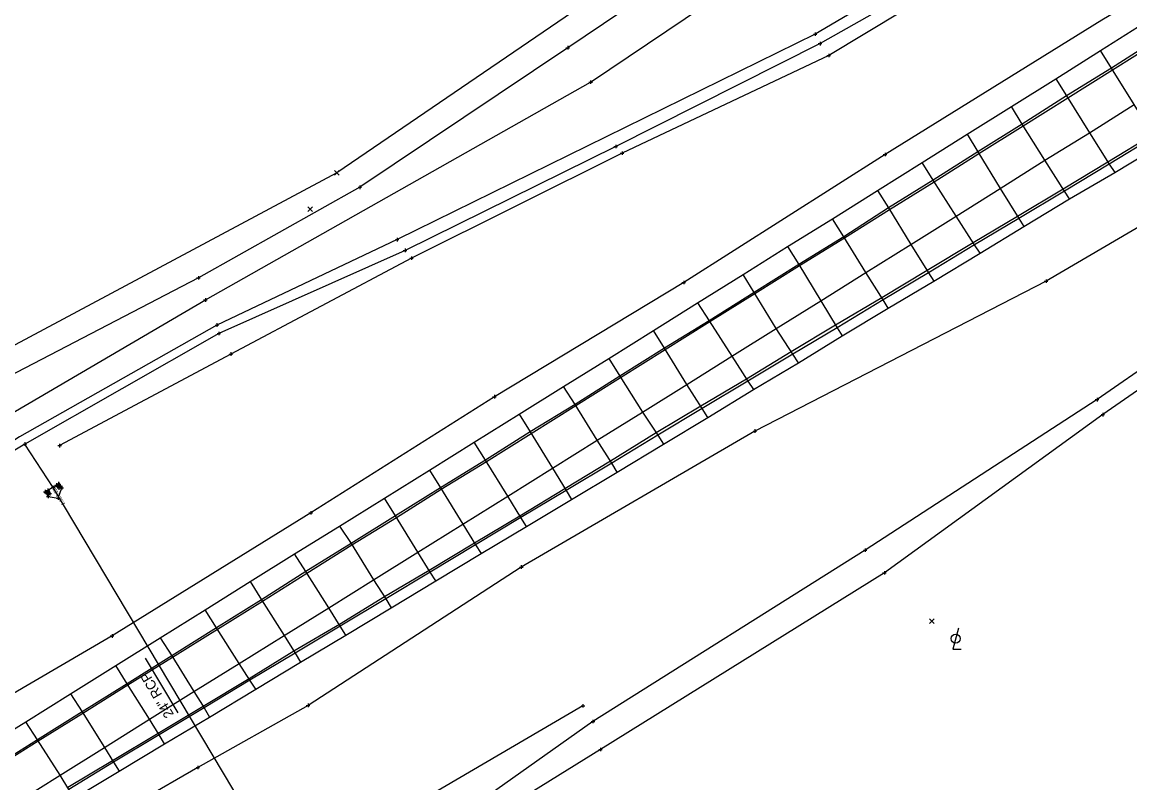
# Model space of a CAD drawing. Extents: x 207090 to 277928, y 600777 to 621109.
# Drawn here: x 260128.7 to 260443.9, y 612310 to 612526.4 of the extents above; entities that cross this region are included whole.
import ezdxf

# ---------------------------------------------------------------- set-up
doc = ezdxf.new("R2010")
doc.units = 0
for name, color, linetype in [('ATDIMS', 7, 'Continuous'), ('BR_X_SV_Abut', 7, 'Continuous'), ('DR_X_Ditch', 7, 'Continuous'), ('DR_X_Headwall', 7, 'Continuous'), ('DR_X_Storm_Sewer', 7, 'Continuous'), ('DR_X_Text', 7, 'Continuous'), ('PM_P_Edge_Line', 7, 'Continuous'), ('PM_P_Lane_Line', 7, 'Continuous'), ('PM_P_Stop_Line', 7, 'Continuous'), ('PM_X_Edge_Line', 7, 'Continuous'), ('PV_X_EOP', 7, 'Continuous'), ('PV_X_Joint', 7, 'Continuous'), ('SC_ProfileRun2', 7, 'Continuous'), ('SV_X_Break_Lines', 7, 'Continuous'), ('SV_X_Terrain_Boundary', 7, 'Continuous'), ('SV_X_Toe_of_Slope', 7, 'Continuous')]:
    doc.layers.add(name, color=color, linetype=linetype)

msp = doc.modelspace()

# ---------------------------------------------------------------- linework, layer by layer
at = {"layer": 'BR_X_SV_Abut'}
msp.add_lwpolyline([(260395.11, 612354.01), (260393.53, 612348.02), (260395.9, 612348.02)], dxfattribs=at)
msp.add_circle((260394.32, 612351.05), 1.3, dxfattribs=at)
at = {"layer": 'DR_X_Ditch'}
for points in [[(260965.76, 612646.3), (260903.89, 612637.59), (260846.21, 612640.66), (260788.21, 612648.32), (260712.08, 612649.13), (260650.53, 612639.93), (260587.71, 612626.03), (260540.4, 612612.72), (260479.82, 612585.9), (260420.03, 612556.72), (260355.72, 612520.34), (260297.57, 612491.05), (260237.63, 612461.5), (260184.65, 612437.88), (260129.42, 612406.42), (260102.9, 612390.57), (260048.34, 612353.6), (259987.69, 612317.19), (259901.67, 612280.03), (259846.55, 612257.32), (259766.99, 612243.21), (259700.14, 612233.86)], [(260980.17, 612470.92), (260981.01, 612514.45), (260979.66, 612549.25), (260978.64, 612555.37), (260908.69, 612562.28), (260843.91, 612565.34), (260762.22, 612565.34), (260693.51, 612556.33), (260617.41, 612526.56), (260561.75, 612499.61), (260504.79, 612467.62), (260434.56, 612419.04), (260368.56, 612376.23), (260291.11, 612327.46), (260243.23, 612293.63), (260221.27, 612279.24), (260214.19, 612277.7), (260205.93, 612279.66)], [(260137.52, 612394.05), (260129.42, 612406.42)]]:
    msp.add_lwpolyline(points, dxfattribs=at)
at = {"layer": 'DR_X_Headwall'}
for p, q in [((260139.64, 612394.15), (260139.21, 612394.9)), ((260136.04, 612392.11), (260135.41, 612392.64))]:
    msp.add_line(p, q, dxfattribs=at)
for points in [[(260139.21, 612394.9), (260138.64, 612394.46), (260139.1, 612393.91), (260139.64, 612394.15)], [(260135.41, 612392.64), (260136, 612393.06), (260136.53, 612392.32), (260136.04, 612392.11)]]:
    msp.add_lwpolyline(points, dxfattribs=at)
at = {"layer": 'DR_X_Storm_Sewer'}
msp.add_line((260205.25, 612280.38), (260137.52, 612394.05), dxfattribs=at)
at = {"layer": 'DR_X_Text'}
msp.add_line((260163.68, 612345.46), (260172.92, 612329.95), dxfattribs=at)
at = {"layer": 'PM_P_Edge_Line'}
for points in [[(259696.19, 612249.37), (259765.47, 612259.57), (259838.8, 612280.72), (259895.42, 612296.27), (259981.86, 612326.52), (260044.12, 612359.9), (260097.15, 612394.53), (260124, 612414.15), (260180.79, 612447.41), (260290.45, 612509.39), (260339.08, 612542.14), (260411.33, 612573.42), (260464.85, 612610.64), (260533.51, 612630.82), (260578.81, 612648.35), (260650.05, 612658.82), (260707.7, 612667.46), (260792.67, 612670.85), (260847.64, 612666.05), (260906.75, 612659.27), (260964.74, 612649.27), (260965.76, 612646.3), (260968.73, 612643.36)], [(260968.73, 612643.36), (260902.74, 612623.34), (260846.31, 612624.57), (260788.34, 612627.98), (260717.27, 612628.63), (260652.8, 612617.17), (260594.62, 612604.25), (260547.65, 612587.51), (260494.06, 612561.48), (260435.88, 612526.99), (260374.24, 612488.77), (260316.93, 612452.38), (260263.05, 612419.87), (260210.79, 612386.85), (260154.25, 612351.81), (260072.66, 612304.2), (260017.02, 612269.09), (259922.67, 612223.96), (259862.48, 612201.08), (259773.94, 612184.08), (259709.47, 612174.19)], [(260996.77, 612473.28), (260998.48, 612548.29), (260988.85, 612564.56), (260906.86, 612575.54), (260845.98, 612579.97), (260758.62, 612581.58), (260693.48, 612576.37), (260609.06, 612545.38), (260552.2, 612527.51), (260484.57, 612490.49), (260420.05, 612452.77), (260337.19, 612410.11), (260270.71, 612371.43), (260210.01, 612332.07), (260178.64, 612314.39), (260129.43, 612285.91), (260084.69, 612259.04), (260045.01, 612227.43), (260009.91, 612199.93)], [(260976.29, 612470.03), (260970.41, 612512.82), (260969.69, 612547.81), (260964.96, 612546.01), (260907.75, 612553.29), (260842.6, 612550.07), (260764.48, 612554.75), (260693.91, 612550.19), (260623.11, 612514), (260563.35, 612494.47), (260507.46, 612464.18), (260436.22, 612414.79), (260374.03, 612369.76), (260293.26, 612319.49), (260245.08, 612289.62), (260217.93, 612273.45)]]:
    msp.add_lwpolyline(points, dxfattribs=at)
at = {"layer": 'PM_P_Lane_Line'}
msp.add_lwpolyline([(260938.98, 612687.53), (260905.67, 612669.26), (260848.25, 612675.38), (260795.41, 612680.92), (260704.93, 612686.62), (260648.32, 612680.48), (260579.89, 612672.71), (260529.06, 612649.65), (260401.46, 612592.11), (260375.93, 612580.54), (260334.15, 612552.98), (260283.92, 612519.17), (260224.77, 612479.46), (260178.82, 612453.71), (260087.02, 612406.01), (260035.98, 612379.41), (259972.28, 612348.23), (259887.97, 612316.7), (259832.19, 612304.21), (259761.95, 612288.66), (259689.59, 612272.72)], dxfattribs=at)
at = {"layer": 'PM_P_Stop_Line'}
for p, q in [((260354.36, 612523.53), (260354.36, 612522.53)), ((260353.86, 612523.03), (260354.86, 612523.03)), ((260354.36, 612523.03), (260354.36, 612523.03)), ((260355.22, 612520.34), (260356.22, 612520.34)), ((260355.72, 612520.84), (260355.72, 612519.84)), ((260355.72, 612520.34), (260355.72, 612520.34)), ((260283.42, 612519.17), (260284.42, 612519.17)), ((260283.92, 612519.67), (260283.92, 612518.67)), ((260283.92, 612519.17), (260283.92, 612519.17)), ((260358.19, 612517.47), (260358.19, 612516.47)), ((260357.69, 612516.97), (260358.69, 612516.97)), ((260358.19, 612516.97), (260358.19, 612516.97)), ((260289.95, 612509.39), (260290.95, 612509.39)), ((260290.45, 612509.89), (260290.45, 612508.89)), ((260290.45, 612509.39), (260290.45, 612509.39)), ((260297.07, 612491.05), (260298.07, 612491.05)), ((260297.57, 612491.55), (260297.57, 612490.55)), ((260297.57, 612491.05), (260297.57, 612491.05)), ((260298.89, 612489.18), (260299.89, 612489.18)), ((260299.39, 612489.68), (260299.39, 612488.68)), ((260299.39, 612489.18), (260299.39, 612489.18)), ((260373.74, 612488.77), (260374.74, 612488.77)), ((260374.24, 612489.27), (260374.24, 612488.27)), ((260374.24, 612488.77), (260374.24, 612488.77)), ((260224.27, 612479.46), (260225.27, 612479.46)), ((260224.77, 612479.96), (260224.77, 612478.96)), ((260224.77, 612479.46), (260224.77, 612479.46)), ((260234.88, 612464.57), (260235.88, 612464.57)), ((260235.38, 612465.07), (260235.38, 612464.07)), ((260235.38, 612464.57), (260235.38, 612464.57)), ((260237.13, 612461.5), (260238.13, 612461.5)), ((260237.63, 612462), (260237.63, 612461)), ((260237.63, 612461.5), (260237.63, 612461.5)), ((260238.97, 612459.31), (260239.97, 612459.31)), ((260239.47, 612459.81), (260239.47, 612458.81)), ((260239.47, 612459.31), (260239.47, 612459.31)), ((260178.82, 612454.21), (260178.82, 612453.21)), ((260178.32, 612453.71), (260179.32, 612453.71)), ((260178.82, 612453.71), (260178.82, 612453.71)), ((260316.43, 612452.38), (260317.43, 612452.38)), ((260316.93, 612452.88), (260316.93, 612451.88)), ((260316.93, 612452.38), (260316.93, 612452.38)), ((260419.55, 612452.77), (260420.55, 612452.77)), ((260420.05, 612453.27), (260420.05, 612452.27)), ((260420.05, 612452.77), (260420.05, 612452.77)), ((260180.79, 612447.91), (260180.79, 612446.91)), ((260180.29, 612447.41), (260181.29, 612447.41)), ((260180.79, 612447.41), (260180.79, 612447.41)), ((260183.57, 612440.26), (260184.57, 612440.26)), ((260184.07, 612440.76), (260184.07, 612439.76)), ((260184.07, 612440.26), (260184.07, 612440.26)), ((260184.65, 612438.38), (260184.65, 612437.38)), ((260184.15, 612437.88), (260185.15, 612437.88)), ((260184.65, 612437.88), (260184.65, 612437.88)), ((260187.54, 612432.01), (260188.54, 612432.01)), ((260188.04, 612432.51), (260188.04, 612431.51)), ((260188.04, 612432.01), (260188.04, 612432.01)), ((260262.55, 612419.87), (260263.55, 612419.87)), ((260263.05, 612420.37), (260263.05, 612419.37)), ((260263.05, 612419.87), (260263.05, 612419.87)), ((260434.56, 612419.54), (260434.56, 612418.54)), ((260434.06, 612419.04), (260435.06, 612419.04)), ((260434.56, 612419.04), (260434.56, 612419.04)), ((260435.72, 612414.79), (260436.72, 612414.79)), ((260436.22, 612415.29), (260436.22, 612414.29)), ((260436.22, 612414.79), (260436.22, 612414.79)), ((260336.69, 612410.11), (260337.69, 612410.11)), ((260337.19, 612410.61), (260337.19, 612409.61)), ((260337.19, 612410.11), (260337.19, 612410.11)), ((260129.42, 612406.92), (260129.42, 612405.92)), ((260128.92, 612406.42), (260129.92, 612406.42)), ((260129.42, 612406.42), (260129.42, 612406.42)), ((260138.81, 612405.97), (260139.81, 612405.97)), ((260139.31, 612406.47), (260139.31, 612405.47)), ((260139.31, 612405.97), (260139.31, 612405.97)), ((260137.92, 612394.74), (260138.92, 612394.74)), ((260138.14, 612394.46), (260139.14, 612394.46)), ((260138.42, 612395.24), (260138.42, 612394.24)), ((260138.42, 612394.74), (260138.42, 612394.74)), ((260138.5, 612395.13), (260139.5, 612395.13)), ((260138.64, 612394.96), (260138.64, 612393.96)), ((260138.64, 612394.46), (260138.64, 612394.46)), ((260138.71, 612394.9), (260139.71, 612394.9)), ((260139, 612395.63), (260139, 612394.63)), ((260139, 612395.13), (260139, 612395.13)), ((260139.1, 612394.41), (260139.1, 612393.41)), ((260139.14, 612394.15), (260140.14, 612394.15)), ((260139.21, 612395.4), (260139.21, 612394.4)), ((260139.21, 612394.9), (260139.21, 612394.9)), ((260139.64, 612394.65), (260139.64, 612393.65)), ((260139.64, 612394.15), (260139.64, 612394.15)), ((260139.91, 612394.49), (260139.91, 612393.49)), ((260134.74, 612392.86), (260135.74, 612392.86)), ((260134.91, 612392.64), (260135.91, 612392.64)), ((260135.24, 612393.36), (260135.24, 612392.36)), ((260135.24, 612392.86), (260135.24, 612392.86)), ((260135.41, 612393.14), (260135.41, 612392.14)), ((260135.41, 612392.64), (260135.41, 612392.64)), ((260135.43, 612393.22), (260136.43, 612393.22)), ((260135.5, 612393.06), (260136.5, 612393.06)), ((260135.54, 612392.11), (260136.54, 612392.11)), ((260135.55, 612391.48), (260136.55, 612391.48)), ((260135.93, 612393.72), (260135.93, 612392.72)), ((260135.93, 612393.22), (260135.93, 612393.22)), ((260136, 612393.56), (260136, 612392.56)), ((260136, 612393.06), (260136, 612393.06)), ((260136.03, 612392.32), (260137.03, 612392.32)), ((260136.04, 612392.61), (260136.04, 612391.61)), ((260136.04, 612392.11), (260136.04, 612392.11)), ((260136.05, 612391.98), (260136.05, 612390.98)), ((260136.05, 612391.48), (260136.05, 612391.48)), ((260136.53, 612392.82), (260136.53, 612391.82)), ((260136.53, 612392.32), (260136.53, 612392.32)), ((260138.43, 612391.05), (260139.43, 612391.05)), ((260138.6, 612393.91), (260139.6, 612393.91)), ((260138.93, 612391.55), (260138.93, 612390.55)), ((260138.93, 612391.05), (260138.93, 612391.05)), ((260139.1, 612393.91), (260139.1, 612393.91)), ((260139.41, 612393.99), (260140.41, 612393.99)), ((260139.91, 612393.99), (260139.91, 612393.99)), ((260210.29, 612386.85), (260211.29, 612386.85)), ((260210.79, 612387.35), (260210.79, 612386.35)), ((260210.79, 612386.85), (260210.79, 612386.85)), ((260368.06, 612376.23), (260369.06, 612376.23)), ((260368.56, 612376.73), (260368.56, 612375.73)), ((260368.56, 612376.23), (260368.56, 612376.23)), ((260270.21, 612371.43), (260271.21, 612371.43)), ((260270.71, 612371.93), (260270.71, 612370.93)), ((260270.71, 612371.43), (260270.71, 612371.43)), ((260373.53, 612369.76), (260374.53, 612369.76)), ((260374.03, 612370.26), (260374.03, 612369.26)), ((260374.03, 612369.76), (260374.03, 612369.76)), ((260153.75, 612351.81), (260154.75, 612351.81)), ((260154.25, 612352.31), (260154.25, 612351.31)), ((260154.25, 612351.81), (260154.25, 612351.81)), ((260209.51, 612332.07), (260210.51, 612332.07)), ((260210.01, 612332.57), (260210.01, 612331.57)), ((260210.01, 612332.07), (260210.01, 612332.07)), ((260287.75, 612331.94), (260288.75, 612331.94)), ((260288.25, 612332.44), (260288.25, 612331.44)), ((260288.25, 612331.94), (260288.25, 612331.94)), ((260291.11, 612327.96), (260291.11, 612326.96)), ((260290.61, 612327.46), (260291.61, 612327.46)), ((260291.11, 612327.46), (260291.11, 612327.46)), ((260292.76, 612319.49), (260293.76, 612319.49)), ((260293.26, 612319.99), (260293.26, 612318.99)), ((260293.26, 612319.49), (260293.26, 612319.49)), ((260178.14, 612314.39), (260179.14, 612314.39)), ((260178.64, 612314.89), (260178.64, 612313.89)), ((260178.64, 612314.39), (260178.64, 612314.39))]:
    msp.add_line(p, q, dxfattribs=at)
at = {"layer": 'PM_X_Edge_Line'}
for p, q in [((260217.56, 612482.94), (260218.89, 612484.28)), ((260217.56, 612484.28), (260218.89, 612482.94)), ((260209.99, 612472.53), (260211.33, 612473.86)), ((260209.99, 612473.86), (260211.33, 612472.53)), ((260386.84, 612355.37), (260388.17, 612356.7)), ((260386.84, 612356.7), (260388.17, 612355.37))]:
    msp.add_line(p, q, dxfattribs=at)
for points in [[(260120.5, 612314.04), (260133.19, 612321.98), (260145.97, 612329.84), (260158.74, 612337.86), (260171.43, 612345.82), (260184.21, 612353.79), (260197.04, 612361.71), (260209.72, 612369.66), (260222.48, 612377.7), (260235.17, 612385.52), (260247.93, 612393.61), (260260.77, 612401.44), (260273.49, 612409.38), (260286.2, 612417.36), (260298.94, 612425.38), (260311.67, 612433.34), (260324.34, 612441.24), (260337.21, 612449.2), (260349.86, 612457.17), (260362.67, 612465.09), (260375.49, 612473.14), (260388.22, 612481.04), (260400.9, 612489.06), (260413.52, 612496.94), (260426.25, 612504.91), (260438.93, 612512.92), (260451.68, 612520.87)], [(260450.47, 612494.35), (260437.67, 612486.59), (260424.94, 612478.97), (260411.88, 612471.19), (260399.33, 612463.64), (260386.24, 612455.75), (260373.31, 612448.01), (260360.16, 612440.24), (260347.5, 612432.67), (260334.83, 612424.86), (260321.76, 612417.15), (260309.08, 612409.57), (260296.1, 612401.54), (260283.14, 612393.69), (260270.31, 612385.93), (260257.36, 612378.22), (260244.49, 612370.43), (260231.76, 612362.95), (260218.93, 612355.05), (260206.01, 612347.45), (260193.23, 612339.63), (260180.19, 612331.77), (260167.36, 612324.09), (260154.37, 612316.33), (260141.62, 612308.67)]]:
    msp.add_lwpolyline(points, dxfattribs=at)
at = {"layer": 'PV_X_EOP'}
for points in [[(260116.92, 612319.48), (260129.68, 612327.37), (260142.42, 612335.33), (260155.28, 612343.37), (260167.92, 612351.27), (260180.74, 612359.29), (260193.56, 612367.28), (260206.19, 612375.13), (260219.01, 612383.09), (260231.77, 612391.01), (260244.54, 612398.99), (260257.26, 612406.95), (260270.08, 612414.92), (260282.71, 612422.8), (260295.59, 612430.76), (260308.31, 612438.72), (260320.84, 612446.56), (260333.85, 612454.62), (260346.5, 612462.6), (260359.29, 612470.53), (260372.12, 612478.56), (260384.76, 612486.47), (260397.56, 612494.57), (260410.2, 612502.46), (260422.83, 612510.35), (260435.51, 612518.34), (260448.19, 612526.39)], [(260143.47, 612305.66), (260156.28, 612313.32), (260169.21, 612321.13), (260181.95, 612328.74), (260195.2, 612336.69), (260207.92, 612344.32), (260220.78, 612352.06), (260233.67, 612359.79), (260246.39, 612367.46), (260259.28, 612375.28), (260272.17, 612382.92), (260284.98, 612390.66), (260298, 612398.44), (260311.18, 612406.4), (260323.8, 612413.92), (260336.8, 612421.91), (260349.58, 612429.48), (260362.06, 612437.2), (260375.15, 612445.09), (260388.11, 612452.74), (260401.31, 612460.69), (260413.75, 612468.26), (260426.73, 612476.21), (260439.61, 612483.66), (260452.33, 612491.36)]]:
    msp.add_lwpolyline(points, dxfattribs=at)
at = {"layer": 'PV_X_Joint'}
for points in [[(260451.34, 612521.41), (260438.64, 612513.4), (260425.9, 612505.47), (260413.24, 612497.39), (260400.6, 612489.55), (260387.93, 612481.51), (260375.19, 612473.63)], [(260452.33, 612491.36), (260450.83, 612493.77), (260445.08, 612503), (260438.64, 612513.4), (260435.51, 612518.34)], [(260422.83, 612510.35), (260425.9, 612505.47), (260432.43, 612495), (260438, 612486.06), (260439.61, 612483.66)], [(260126.73, 612304.22), (260139.48, 612312.18), (260152.08, 612320.08), (260164.9, 612328.12), (260177.56, 612335.99), (260190.41, 612344), (260203.21, 612351.96), (260215.95, 612359.82), (260228.67, 612367.8), (260241.25, 612375.69), (260254.06, 612383.63), (260266.86, 612391.62), (260279.57, 612399.56), (260292.3, 612407.52), (260305.21, 612415.45), (260317.83, 612423.4), (260330.58, 612431.38), (260343.29, 612439.27), (260355.97, 612447.2), (260368.8, 612455.23), (260381.58, 612463.15), (260394.44, 612471.21), (260406.96, 612479.12), (260419.75, 612487.16), (260432.43, 612495), (260445.08, 612503)], [(260426.73, 612476.21), (260425.31, 612478.39), (260419.75, 612487.16), (260413.24, 612497.39), (260410.2, 612502.46)], [(260450.83, 612493.77), (260438, 612486.06), (260425.31, 612478.39), (260412.26, 612470.58), (260399.71, 612463.06), (260386.63, 612455.12), (260373.67, 612447.43), (260360.59, 612439.52), (260347.94, 612431.97), (260335.18, 612424.32), (260322.16, 612416.5), (260309.53, 612408.9), (260296.46, 612400.97), (260283.47, 612393.15), (260270.59, 612385.47), (260257.69, 612377.7), (260244.77, 612369.98), (260232.12, 612362.39), (260219.18, 612354.64), (260206.36, 612346.88), (260193.5, 612339.22), (260180.44, 612331.37), (260167.64, 612323.64), (260154.64, 612315.89), (260141.92, 612308.17)], [(260397.56, 612494.57), (260400.6, 612489.55), (260406.96, 612479.12), (260412.26, 612470.58), (260413.75, 612468.26)], [(260401.31, 612460.69), (260399.71, 612463.06), (260394.44, 612471.21), (260387.93, 612481.51), (260384.76, 612486.47)], [(260372.12, 612478.56), (260375.19, 612473.63), (260381.58, 612463.15), (260386.63, 612455.12), (260388.11, 612452.74)], [(260375.19, 612473.63), (260362.48, 612465.39), (260349.67, 612457.48), (260337.01, 612449.53), (260324.22, 612441.42), (260311.46, 612433.68), (260298.71, 612425.75), (260286, 612417.68), (260273.2, 612409.85), (260260.51, 612401.87), (260247.73, 612393.94), (260234.91, 612385.95), (260222.25, 612378.07), (260209.43, 612370.13), (260196.79, 612362.09), (260184, 612354.12), (260171.24, 612346.13), (260158.52, 612338.21), (260145.73, 612330.23), (260133.01, 612322.27), (260120.34, 612314.28)], [(260375.15, 612445.09), (260373.67, 612447.43), (260368.8, 612455.23), (260362.48, 612465.39), (260359.29, 612470.53)], [(260346.5, 612462.6), (260349.67, 612457.48), (260355.97, 612447.2), (260360.59, 612439.52), (260362.06, 612437.2)], [(260349.58, 612429.48), (260347.94, 612431.97), (260343.29, 612439.27), (260337.01, 612449.53), (260333.85, 612454.62)], [(260320.84, 612446.56), (260324.22, 612441.42), (260330.58, 612431.38), (260335.18, 612424.32), (260336.8, 612421.91)], [(260323.8, 612413.92), (260322.16, 612416.5), (260317.83, 612423.4), (260311.46, 612433.68), (260308.31, 612438.72)], [(260295.59, 612430.76), (260298.71, 612425.75), (260305.21, 612415.45), (260309.53, 612408.9), (260311.18, 612406.4)], [(260298, 612398.44), (260296.46, 612400.97), (260292.3, 612407.52), (260286, 612417.68), (260282.71, 612422.8)], [(260270.08, 612414.92), (260273.2, 612409.85), (260279.57, 612399.56), (260283.47, 612393.15), (260284.98, 612390.66)], [(260272.17, 612382.92), (260270.59, 612385.47), (260266.86, 612391.62), (260260.51, 612401.87), (260257.26, 612406.95)], [(260244.54, 612398.99), (260247.73, 612393.94), (260254.06, 612383.63), (260257.69, 612377.7), (260259.28, 612375.28)], [(260246.39, 612367.46), (260244.77, 612369.98), (260241.25, 612375.69), (260234.91, 612385.95), (260231.77, 612391.01)], [(260219.01, 612383.09), (260222.25, 612378.07), (260228.67, 612367.8), (260232.12, 612362.39), (260233.67, 612359.79)], [(260220.78, 612352.06), (260219.18, 612354.64), (260215.95, 612359.82), (260209.43, 612370.13), (260206.19, 612375.13)], [(260193.56, 612367.28), (260196.79, 612362.09), (260203.21, 612351.96), (260206.36, 612346.88), (260207.92, 612344.32)], [(260195.2, 612336.69), (260193.5, 612339.22), (260190.41, 612344), (260184, 612354.12), (260180.74, 612359.29)], [(260167.92, 612351.27), (260171.24, 612346.13), (260177.56, 612335.99), (260180.44, 612331.37), (260181.95, 612328.74)], [(260169.21, 612321.13), (260167.64, 612323.64), (260164.9, 612328.12), (260158.52, 612338.21), (260155.28, 612343.37)], [(260142.42, 612335.33), (260145.73, 612330.23), (260152.08, 612320.08), (260154.64, 612315.89), (260156.28, 612313.32)], [(260143.47, 612305.66), (260141.92, 612308.17), (260139.48, 612312.18), (260133.01, 612322.27), (260129.68, 612327.37)]]:
    msp.add_lwpolyline(points, dxfattribs=at)
at = {"layer": 'SC_ProfileRun2'}
for p, q in [((260137.02, 612394.05), (260138.02, 612394.05)), ((260137.52, 612394.55), (260137.52, 612393.55)), ((260137.52, 612394.05), (260137.52, 612394.05))]:
    msp.add_line(p, q, dxfattribs=at)
at = {"layer": 'SV_X_Break_Lines'}
msp.add_lwpolyline([(260135.93, 612393.22), (260135.24, 612392.86), (260136.05, 612391.48), (260138.93, 612391.05), (260139.91, 612393.99), (260139, 612395.13), (260138.42, 612394.74)], close=True, dxfattribs=at)
at = {"layer": 'SV_X_Terrain_Boundary'}
msp.add_lwpolyline([(260983.37, 612812.65), (260938.98, 612687.53), (260903.8, 612676.08), (260828.62, 612686.24), (260720.8, 612697.94), (260579.24, 612680.21), (260471.8, 612633.29), (260370.94, 612586.63), (260308.24, 612545.06), (260218.23, 612483.61), (260121.1, 612431.7), (260019.22, 612378.89), (259908.73, 612332.42)], dxfattribs=at)
at = {"layer": 'SV_X_Toe_of_Slope'}
for points in [[(260846.78, 612643.82), (260788.62, 612651.68), (260711.88, 612651.68), (260649.51, 612644.01), (260586.77, 612629.44), (260538.54, 612616.8), (260477.73, 612589.44), (260417.65, 612560.33), (260354.36, 612523.03), (260235.38, 612464.57), (260184.07, 612440.26), (260127.9, 612408.42), (260047.32, 612354.89), (259986.34, 612321), (259898.57, 612287.97), (259845.49, 612261.31), (259767.02, 612246.06), (259699.57, 612235.7)], [(260846.79, 612637.04), (260787.74, 612645.4), (260713.66, 612644.84), (260650.44, 612637.88), (260588.47, 612623.19), (260541.01, 612608.57), (260480.87, 612584.7), (260421.09, 612554.93), (260358.19, 612516.97), (260299.39, 612489.18), (260239.47, 612459.31), (260188.04, 612432.01), (260139.31, 612405.97)], [(260288.25, 612331.94), (260236.48, 612301.69), (260209.62, 612282.46)]]:
    msp.add_lwpolyline(points, dxfattribs=at)

# ---------------------------------------------------------------- texts
at = {"layer": 'ATDIMS'}
msp.add_text("1,127.32'", height=1, rotation=120.7903, dxfattribs=at).set_placement((260140.91, 612389.34))
at = {"layer": 'DR_X_Text'}
msp.add_text('24" RCP', height=2.8, rotation=120.7903, dxfattribs=at).set_placement((260171.92, 612329.49))

doc.saveas('drawing.dxf')
